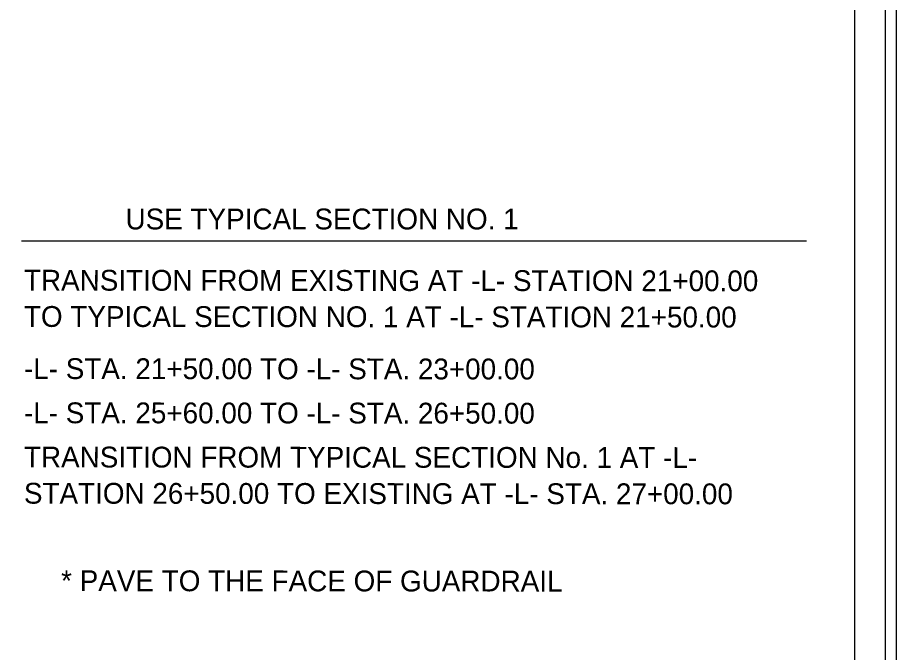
# Model space of a CAD drawing. Extents: x 1497225 to 1499181, y 579958 to 582278.
# Drawn here: x 1498550.6 to 1498909.2, y 581755.1 to 582014.3 of the extents above; entities that cross this region are included whole.
import ezdxf

# ---------------------------------------------------------------- set-up
doc = ezdxf.new("R2010")
doc.units = 0
for name, color, linetype in [('Old_Level_1', 7, 'Continuous'), ('Sheet Plot Border Inside CELL', 7, 'Continuous'), ('Sheet Plot Border Outside CELL', 7, 'Continuous'), ('Sheet Typical CELL', 7, 'Continuous'), ('Typical Text Label CELL', 7, 'Continuous')]:
    doc.layers.add(name, color=color, linetype=linetype)

msp = doc.modelspace()

# ---------------------------------------------------------------- linework, layer by layer
at = {"layer": 'Sheet Plot Border Inside CELL'}
msp.add_lwpolyline([(1498904.73, 582255.51), (1497238.23, 582255.51), (1497238.23, 581200.41), (1498904.73, 581200.41)], close=True, dxfattribs=at)
at = {"layer": 'Sheet Plot Border Outside CELL'}
msp.add_lwpolyline([(1498909.23, 582277.96), (1497225.23, 582277.96), (1497225.23, 581177.96), (1498909.23, 581177.96)], close=True, dxfattribs=at)
at = {"layer": 'Sheet Typical CELL'}
msp.add_lwpolyline([(1498892.23, 582252.96), (1497392.23, 582252.96), (1497392.23, 581202.96), (1498892.23, 581202.96)], close=True, dxfattribs=at)
at = {"layer": 'Typical Text Label CELL'}
msp.add_line((1498552.17, 581923.17), (1498872.52, 581923.17), dxfattribs=at)

# ---------------------------------------------------------------- texts
at = {"layer": 'Old_Level_1'}
for s, p in [('TRANSITION FROM EXISTING AT -L- STATION 21+00.00', (1498553.17, 581902.85)), ('TO TYPICAL SECTION NO. 1 AT -L- STATION 21+50.00', (1498553.16, 581888.05)), ('-L- STA. 21+50.00 TO -L- STA. 23+00.00', (1498553.17, 581866.76)), ('-L- STA. 25+60.00 TO -L- STA. 26+50.00', (1498553.17, 581848.72)), ('TRANSITION FROM TYPICAL SECTION No. 1 AT -L-', (1498553.17, 581830.67)), ('STATION 26+50.00 TO EXISTING AT -L- STA. 27+00.00', (1498553.16, 581815.87)), ('* PAVE TO THE FACE OF GUARDRAIL', (1498568.33, 581780.16))]:
    msp.add_text(s, height=8.5, rotation=359.9492, dxfattribs=at).set_placement(p)
at = {"layer": 'Typical Text Label CELL'}
msp.add_text('USE TYPICAL SECTION NO. 1', height=8.5, dxfattribs=at).set_placement((1498594.62, 581927.84))

doc.saveas('drawing.dxf')
